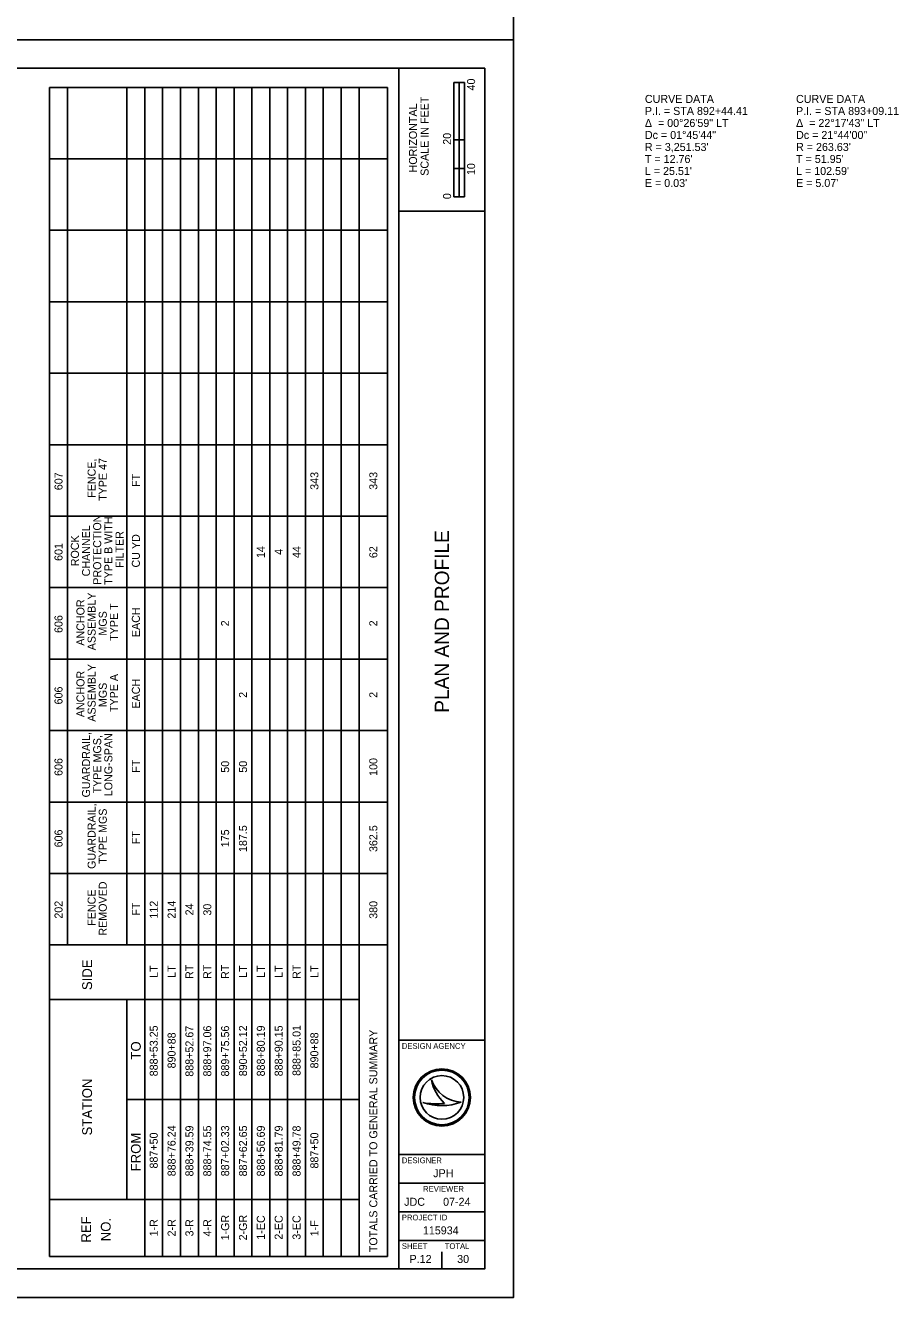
# Model space of a CAD drawing. Extents: x 0 to 2520, y -440 to 502.
# Drawn here: x 509.4 to 814.6, y -440 to 5 of the extents above; entities that cross this region are included whole.
import ezdxf

# ---------------------------------------------------------------- set-up
doc = ezdxf.new("R2010")
doc.units = 0
for name, color, linetype in [('Default', 7, 'Continuous'), ('DR_X_Culvert', 7, 'Continuous'), ('PF_P_Grade_Line', 7, 'Continuous'), ('PF_X_Ground_Line', 7, 'Continuous'), ('TX_P_1', 7, 'Continuous')]:
    doc.layers.add(name, color=color, linetype=linetype)

msp = doc.modelspace()

# ---------------------------------------------------------------- linework, layer by layer
at = {"layer": 'DR_X_Culvert'}
for points in [[(0, 0), (680, 0), (680, 440), (0, 440)], [(0, -440), (680, -440), (680, 0), (0, 0)]]:
    msp.add_lwpolyline(points, close=True, dxfattribs=at)
at = {"layer": 'PF_X_Ground_Line'}
for p, q in [((517.87, -16.67), (517.87, -425.68)), ((636.03, -16.67), (517.87, -16.67)), ((524.11, -16.67), (524.11, -316.67)), ((544.91, -16.67), (544.91, -316.67)), ((551.15, -16.67), (551.15, -425.68)), ((557.39, -16.67), (557.39, -425.68)), ((563.63, -16.67), (563.63, -425.68)), ((569.87, -16.67), (569.87, -425.68)), ((576.11, -16.67), (576.11, -425.68)), ((582.35, -16.67), (582.35, -425.68)), ((588.59, -16.67), (588.59, -425.68)), ((594.83, -16.67), (594.83, -425.68)), ((601.07, -16.67), (601.07, -425.68)), ((607.31, -16.67), (607.31, -425.68)), ((613.55, -16.67), (613.55, -425.68)), ((619.79, -16.67), (619.79, -425.68)), ((626.03, -16.67), (626.03, -425.68)), ((636.03, -16.67), (636.03, -425.68)), ((659.13, -55), (659.13, -15)), ((662.88, -15), (659.13, -15)), ((659.13, -35), (659.13, -15)), ((659.13, -15), (661, -15)), ((661, -15), (661.02, -15)), ((661.02, -15), (661.02, -35)), ((662.88, -15), (662.88, -55)), ((661.02, -35), (659.13, -35)), ((662.87, -35), (661, -35)), ((661, -35), (661, -45)), ((662.87, -45), (662.87, -35)), ((636.03, -41.67), (517.87, -41.67)), ((661, -45), (659.13, -45)), ((659.13, -45), (659.13, -55)), ((661, -55), (661, -45)), ((661, -45), (662.87, -45)), ((662.88, -55), (659.13, -55)), ((659.13, -55), (661, -55)), ((636.03, -66.67), (517.87, -66.67)), ((636.03, -91.67), (517.87, -91.67)), ((636.03, -116.67), (517.87, -116.67)), ((636.03, -141.67), (517.87, -141.67)), ((636.03, -166.67), (517.87, -166.67)), ((636.03, -191.67), (517.87, -191.67)), ((636.03, -216.67), (517.87, -216.67)), ((636.03, -241.67), (517.87, -241.67)), ((636.03, -266.67), (517.87, -266.67)), ((636.03, -291.67), (517.87, -291.67)), ((636.03, -316.67), (517.87, -316.67)), ((517.87, -335.68), (626.03, -335.68)), ((544.91, -335.68), (544.91, -405.68)), ((651.35, -363.81), (651.35, -363.81)), ((544.91, -370.68), (626.03, -370.68)), ((648.34, -371.81), (648.34, -371.81)), ((655, -370), (655, -370)), ((661.75, -371.63), (661.75, -371.63)), ((517.87, -405.68), (626.03, -405.68)), ((517.87, -425.68), (636.03, -425.68)), ((647.5, -426.5), (647.5, -426.5)), ((655, -430), (655, -424))]:
    msp.add_line(p, q, dxfattribs=at)
for radius in [10, 9.54, 9.54, 7.64]:
    msp.add_circle((655, -370), radius, dxfattribs=at)
for centre, radius, start, end in [((662.32, -360.05), 11.6, 198.9257, 198.9319), ((666.93, -360.6), 15.91, 191.6379, 191.6421), ((662.32, -360.05), 11.6, 198.9319, 267.1657), ((666.93, -360.6), 15.91, 191.6421, 226.0947), ((654.79, -352.6), 20.26, 251.4576, 290.0832), ((652.96, -346.91), 25.32, 259.4964, 259.4995), ((654.79, -352.6), 20.26, 251.4527, 251.4576), ((652.96, -346.91), 25.32, 259.4995, 276.6672)]:
    msp.add_arc(centre, radius, start, end, dxfattribs=at)
at = {"layer": 'TX_P_1'}
for p, q in [((640, -430), (640, -10)), ((640, -60), (670, -60)), ((640, -350), (670, -350)), ((640, -390), (670, -390)), ((640, -400), (670, -400)), ((640, -410), (670, -410)), ((640, -420), (670, -420))]:
    msp.add_line(p, q, dxfattribs=at)
msp.add_lwpolyline([(30, -10), (670, -10), (670, -430), (30, -430)], close=True, dxfattribs=at)

# ---------------------------------------------------------------- texts
at = {"layer": 'Default'}
for s, p in [('CURVE DATA', (725.96, -22.11)), ('CURVE DATA', (778.8, -22.11)), ('P.I. = STA 892+44.41', (725.96, -26.31)), ('P.I. = STA 893+09.11', (778.8, -26.31)), ('Δ  = 00°26\'59" LT', (725.96, -30.51)), ('Δ  = 22°17\'43" LT', (778.8, -30.51)), ('Dc = 01°45\'44"', (725.96, -34.71)), ('Dc = 21°44\'00"', (778.8, -34.71)), ("R = 3,251.53'", (725.96, -38.91)), ("R = 263.63'", (778.8, -38.91)), ("T = 12.76'", (725.96, -43.11)), ("L = 25.51'", (725.96, -47.31)), ("T = 51.95'", (778.8, -43.11)), ("L = 102.59'", (778.8, -47.31)), ("E = 0.03'", (725.96, -51.51)), ("E = 5.07'", (778.8, -51.51))]:
    msp.add_text(s, height=2.8, dxfattribs=at).set_placement(p)
at = {"layer": 'PF_P_Grade_Line'}
for s, p in [('FENCE,', (533.96, -160.24)), ('TYPE 47', (537.86, -161.33)), ('607', (522.39, -157.58)), ('FT', (549.43, -156.41)), ('343', (611.83, -157.44)), ('343', (632.43, -157.44)), ('PROTECTION', (535.91, -190.64)), ('TYPE B WITH', (539.81, -190.69)), ('ROCK', (528.11, -184.18)), ('CHANNEL', (532.01, -187.72)), ('FILTER', (543.72, -184.79)), ('CU YD', (549.43, -184.62)), ('601', (522.39, -182.32)), ('14', (593.11, -181.32)), ('44', (605.59, -181.32)), ('62', (632.43, -181.33)), ('4', (599.35, -180.2)), ('ASSEMBLY', (533.96, -213.57)), ('ANCHOR', (530.06, -211.98)), ('MGS', (537.86, -208.44)), ('TYPE T', (541.76, -210.26)), ('EACH', (549.43, -208.96)), ('606', (522.39, -207.52)), ('2', (580.63, -205.21)), ('2', (632.43, -205.21)), ('ANCHOR', (530.06, -236.98)), ('ASSEMBLY', (533.96, -238.57)), ('TYPE A', (541.76, -235.18)), ('606', (522.39, -232.52)), ('MGS', (537.86, -233.44)), ('EACH', (549.43, -233.96)), ('2', (586.87, -230.21)), ('2', (632.43, -230.21)), ('GUARDRAIL,', (532.01, -265.05)), ('TYPE MGS,', (535.91, -263.64)), ('LONG-SPAN', (539.81, -264.64)), ('606', (522.39, -257.52)), ('FT', (549.43, -256.41)), ('50', (580.63, -256.4)), ('50', (586.87, -256.4)), ('100', (632.43, -257.51)), ('GUARDRAIL,', (533.96, -290.05)), ('TYPE MGS', (537.86, -288.3)), ('187.5', (586.87, -284.15)), ('362.5', (632.43, -284.15)), ('606', (522.39, -282.52)), ('FT', (549.43, -281.41)), ('175', (580.63, -282.47)), ('FENCE', (533.96, -309.95)), ('REMOVED', (537.86, -313.39)), ('202', (522.39, -307.45)), ('FT', (549.43, -306.41)), ('112', (555.67, -307.45)), ('214', (561.91, -307.44)), ('24', (568.15, -306.32)), ('30', (574.39, -306.4)), ('380', (632.43, -307.51)), ('LT', (555.67, -328.16)), ('LT', (561.91, -328.16)), ('RT', (568.15, -328.55)), ('RT', (574.39, -328.55)), ('RT', (580.63, -328.55)), ('LT', (586.87, -328.16)), ('LT', (593.11, -328.16)), ('LT', (599.35, -328.16)), ('RT', (605.59, -328.55)), ('LT', (611.83, -328.16)), ('888+53.25', (555.67, -362.61)), ('888+52.67', (568.15, -362.73)), ('888+97.06', (574.39, -362.67)), ('889+75.56', (580.63, -362.67)), ('890+52.12', (586.87, -362.59)), ('888+80.19', (593.11, -362.63)), ('888+90.15', (599.35, -362.61)), ('888+85.01', (605.59, -362.46)), ('890+88', (561.91, -359.85)), ('890+88', (611.83, -359.85)), ('887+50', (555.67, -394.86)), ('888+76.24', (561.91, -397.58)), ('888+39.59', (568.15, -397.63)), ('888+74.55', (574.39, -397.61)), ('887+02.33', (580.63, -397.58)), ('887+62.65', (586.87, -397.61)), ('888+56.69', (593.11, -397.63)), ('888+81.79', (599.35, -397.63)), ('888+49.78', (605.59, -397.64)), ('887+50', (611.83, -394.86)), ('1-R', (555.67, -418.62)), ('2-R', (561.91, -418.62)), ('3-R', (568.15, -418.62)), ('4-R', (574.39, -418.62)), ('1-GR', (580.63, -420.01)), ('2-GR', (586.87, -420.01)), ('1-EC', (593.11, -419.75)), ('2-EC', (599.35, -419.75)), ('3-EC', (605.59, -419.75)), ('1-F', (611.83, -418.56))]:
    msp.add_text(s, height=2.8, rotation=90, dxfattribs=at).set_placement(p)
at = {"layer": 'PF_X_Ground_Line'}
for s, height, p in [('40', 2.8, (666.61, -17.75)), ('SCALE IN FEET', 2.8, (650.35, -47.59)), ('HORIZONTAL', 2.8, (646.3, -46.42)), ('20', 2.8, (658.21, -36.75)), ('10', 2.8, (666.61, -47.35)), ('0', 2.8, (658.21, -55.77)), ('PLAN AND PROFILE', 5, (657.5, -235.45)), ('SIDE', 3.435, (532.71, -332.45)), ('TOTALS CARRIED TO GENERAL SUMMARY', 2.8, (632.43, -424.12)), ('TO', 3.435, (549.75, -356.75)), ('STATION', 3.435, (532.71, -383.29)), ('FROM', 3.435, (549.75, -395.85)), ('REF', 3.436, (532.36, -420.78)), ('NO.', 3.436, (539.23, -420.31))]:
    msp.add_text(s, height=height, rotation=90, dxfattribs=at).set_placement(p)
for s, height, p in [('DESIGN AGENCY', 2, (641, -353)), ('DESIGNER', 2, (641, -393)), ('JPH', 2.8, (651.97, -397.9)), ('REVIEWER', 2, (648.44, -403)), ('JDC', 2.8, (641.82, -407.9)), ('07-24', 2.8, (655.42, -407.9)), ('PROJECT ID', 2, (641, -413)), ('115934', 2.8, (648.36, -417.9)), ('SHEET', 2, (641, -423)), ('TOTAL', 2, (656, -423)), ('P.12', 2.8, (643.69, -427.9)), ('30', 2.8, (660.34, -427.9))]:
    msp.add_text(s, height=height, dxfattribs=at).set_placement(p)

doc.saveas('drawing.dxf')
